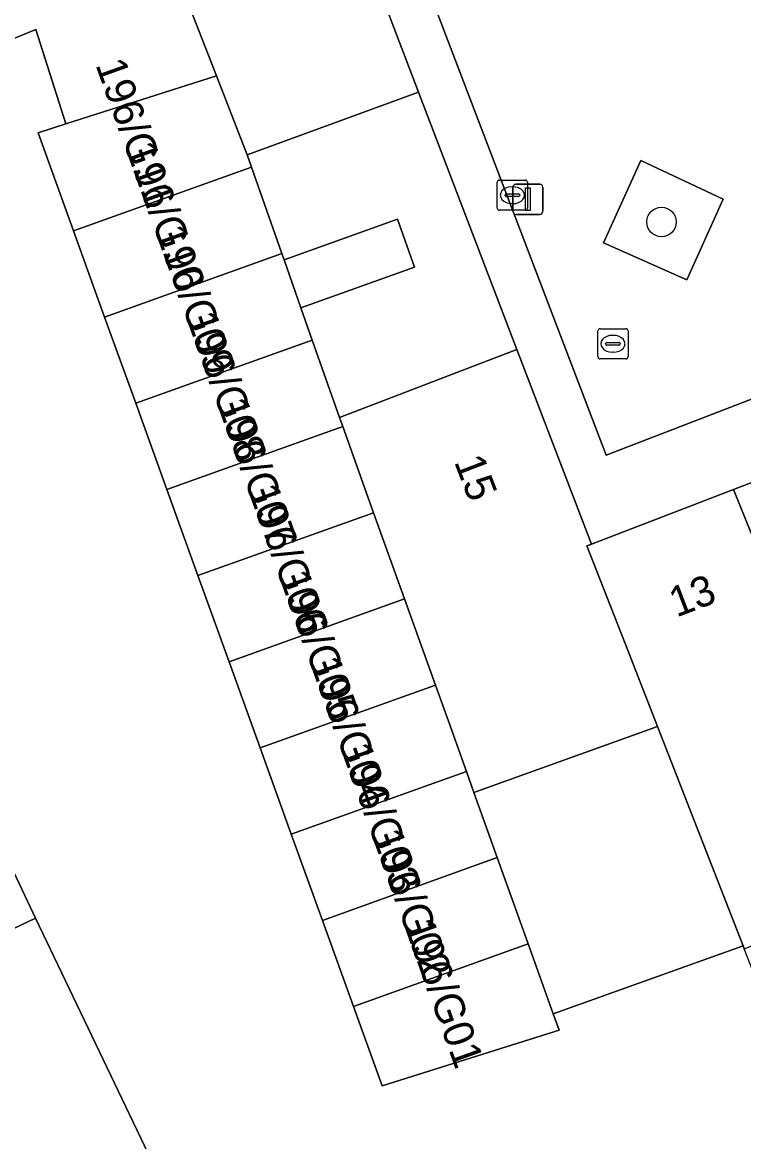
# Model space of a CAD drawing. Extents: x 159262 to 160143, y 383399 to 384319.
# Drawn here: x 159589.68 to 159613.57, y 383605.01 to 383642.07 of the extents above; entities that cross this region are included whole.
import ezdxf

# ---------------------------------------------------------------- set-up
doc = ezdxf.new("R2010")
doc.units = 0
for name, color, linetype in [('IMGEO_Boom', 7, 'Continuous'), ('IMGEO_Erf', 7, 'Continuous'), ('IMGEO_Groenvoorziening', 7, 'Continuous'), ('IMGEO_Kolk', 7, 'Continuous'), ('IMGEO_Lichtmast', 7, 'Continuous'), ('IMGEO_Muur', 7, 'Continuous'), ('IMGEO_Pand', 7, 'Continuous'), ('IMGEO_Pand_nummerreeks', 7, 'Continuous'), ('IMGEO_Rijbaan_lokaal_open', 7, 'Continuous'), ('IMGEO_Rioolput', 7, 'Continuous'), ('IMGEO_Voetpad_open', 7, 'Continuous')]:
    doc.layers.add(name, color=color, linetype=linetype)

msp = doc.modelspace()

# ---------------------------------------------------------------- linework, layer by layer
at = {"layer": 'IMGEO_Boom'}
msp.add_circle((159610.847, 383635.461), 0.489, dxfattribs=at)
at = {"layer": 'IMGEO_Erf'}
msp.add_lwpolyline([(159588.581, 383641.206), (159590.125, 383641.835), (159591.119, 383638.714), (159596.105, 383640.302), (159593.386, 383647.285), (159589.424, 383645.776)], dxfattribs=at)
for points in [[(159602.802, 383639.758), (159597.123, 383637.687), (159597.268, 383637.276), (159598.274, 383634.414), (159598.348, 383634.205), (159602.099, 383635.55), (159602.666, 383633.968), (159598.905, 383632.62), (159599.281, 383631.552), (159600.184, 383628.984), (159606.055, 383631.241)], [(159612.677, 383613.722), (159610.713, 383618.753), (159604.633, 383616.574), (159605.408, 383614.412), (159606.431, 383611.557), (159607.262, 383609.239), (159613.547, 383611.493)]]:
    msp.add_lwpolyline(points, close=True, dxfattribs=at)
at = {"layer": 'IMGEO_Groenvoorziening'}
msp.add_lwpolyline([(159611.686, 383633.54), (159612.89, 383636.214), (159610.165, 383637.494), (159608.931, 383634.775)], close=True, dxfattribs=at)
at = {"layer": 'IMGEO_Kolk'}
for p, q in [((159605.483, 383636.848), (159606.335, 383636.848)), ((159605.408, 383635.922), (159605.408, 383636.774)), ((159605.896, 383636.628), (159605.921, 383636.628)), ((159606.409, 383636.774), (159606.409, 383635.922)), ((159605.667, 383636.342), (159605.667, 383636.354)), ((159606.105, 383636.305), (159605.707, 383636.305)), ((159605.71, 383636.391), (159606.108, 383636.391)), ((159606.151, 383636.354), (159606.151, 383636.342)), ((159606.335, 383635.848), (159605.483, 383635.848)), ((159605.919, 383636.068), (159605.894, 383636.068))]:
    msp.add_line(p, q, dxfattribs=at)
for points in [[(159605.483, 383636.848), (159606.335, 383636.848)], [(159605.408, 383635.922), (159605.408, 383636.774)], [(159606.409, 383636.774), (159606.409, 383635.922)], [(159606.335, 383635.848), (159605.483, 383635.848)]]:
    msp.add_lwpolyline(points, dxfattribs=at)
for centre, radius, start, end in [((159605.485, 383636.772), 0.0765, 91.552, 178.448), ((159605.485, 383636.772), 0.0765, 91.552, 178.448), ((159606.333, 383636.772), 0.0765, 1.552, 88.448), ((159606.333, 383636.772), 0.0765, 1.552, 88.448), ((159605.707, 383636.351), 0.0403, 85.8775, 175.7526), ((159605.704, 383636.341), 0.0366, 178.938, 274.7102), ((159606.108, 383636.348), 0.043, 264.8664, 352.4533), ((159606.112, 383636.353), 0.0386, 1.7309, 96.639), ((159605.485, 383635.924), 0.0765, 181.552, 268.448), ((159605.485, 383635.924), 0.0765, 181.552, 268.448), ((159606.333, 383635.924), 0.0765, 271.552, 358.448), ((159606.333, 383635.924), 0.0765, 271.552, 358.448)]:
    msp.add_arc(centre, radius, start, end, dxfattribs=at)
for centre, major_axis, ratio, start_param, end_param in [((159605.895, 383636.348), (-0.387, 0.002), 0.722429, 4.712389, 7.853982), ((159605.92, 383636.348), (-0.39, 0.002), 0.717154, 1.570796, 4.712389)]:
    msp.add_ellipse(centre, major_axis=major_axis, ratio=ratio, start_param=start_param, end_param=end_param, dxfattribs=at)
at = {"layer": 'IMGEO_Lichtmast'}
for p, q in [((159605.922, 383635.813), (159605.922, 383636.613)), ((159605.922, 383636.613), (159605.922, 383635.813)), ((159606.022, 383636.713), (159606.812, 383636.713)), ((159606.812, 383636.713), (159606.022, 383636.713)), ((159606.912, 383636.613), (159606.912, 383635.813)), ((159606.912, 383635.813), (159606.912, 383636.613)), ((159606.812, 383635.713), (159606.022, 383635.713)), ((159606.022, 383635.713), (159606.812, 383635.713))]:
    msp.add_line(p, q, dxfattribs=at)
msp.add_lwpolyline([(159606.342, 383636.588), (159606.492, 383636.588), (159606.492, 383635.838), (159606.342, 383635.838), (159606.342, 383636.588)], dxfattribs=at)
for centre, start, end in [((159606.022, 383636.613), 90, 180), ((159606.022, 383636.613), 90, 180), ((159606.812, 383636.613), 0, 90), ((159606.812, 383636.613), 360, 90), ((159606.022, 383635.813), 180, 270), ((159606.022, 383635.813), 180, 270), ((159606.812, 383635.813), 270, 0), ((159606.812, 383635.813), 270, 0)]:
    msp.add_arc(centre, 0.1, start, end, dxfattribs=at)
at = {"layer": 'IMGEO_Muur'}
msp.add_lwpolyline([(159602.802, 383639.758), (159606.055, 383631.241)], dxfattribs=at)
at = {"layer": 'IMGEO_Pand'}
for points in [[(159599.106, 383649.464), (159596.696, 383648.546), (159593.386, 383647.285), (159596.105, 383640.302), (159597.123, 383637.687), (159602.802, 383639.758)], [(159596.105, 383640.302), (159591.119, 383638.714), (159590.201, 383638.415), (159591.375, 383635.164), (159597.268, 383637.276), (159597.123, 383637.687)], [(159598.274, 383634.414), (159597.268, 383637.276), (159591.375, 383635.164), (159592.405, 383632.31)], [(159602.099, 383635.55), (159598.348, 383634.205), (159598.905, 383632.62), (159602.666, 383633.968)], [(159598.905, 383632.62), (159598.348, 383634.205), (159598.274, 383634.414), (159592.405, 383632.31), (159593.435, 383629.457), (159599.281, 383631.552)], [(159599.281, 383631.552), (159593.435, 383629.457), (159594.465, 383626.603), (159600.289, 383628.691), (159600.184, 383628.984)], [(159608.533, 383624.793), (159606.055, 383631.241), (159600.184, 383628.984), (159600.289, 383628.691), (159601.313, 383625.835), (159602.336, 383622.98), (159603.36, 383620.124), (159603.789, 383618.926), (159604.384, 383617.268), (159604.633, 383616.574), (159610.713, 383618.753), (159609.738, 383621.249), (159608.376, 383624.733)], [(159600.289, 383628.691), (159594.465, 383626.603), (159595.495, 383623.75), (159601.313, 383625.835)], [(159618.101, 383628.463), (159613.236, 383626.597), (159617.654, 383615.665), (159622.507, 383617.561)], [(159613.236, 383626.597), (159608.533, 383624.793), (159608.376, 383624.733), (159609.738, 383621.249), (159610.713, 383618.753), (159612.677, 383613.722), (159613.547, 383611.493), (159613.585, 383611.396), (159618.589, 383613.35), (159617.654, 383615.665)], [(159602.336, 383622.98), (159601.313, 383625.835), (159595.495, 383623.75), (159596.525, 383620.896)], [(159602.336, 383622.98), (159596.525, 383620.896), (159597.555, 383618.043), (159603.36, 383620.124)], [(159598.585, 383615.19), (159604.384, 383617.268), (159603.789, 383618.926), (159603.36, 383620.124), (159597.555, 383618.043)], [(159604.633, 383616.574), (159604.384, 383617.268), (159598.585, 383615.19), (159599.615, 383612.336), (159605.408, 383614.412)], [(159583.235, 383612.589), (159584.598, 383609.776), (159590.113, 383612.405), (159588.754, 383615.263)], [(159606.431, 383611.557), (159605.408, 383614.412), (159599.615, 383612.336), (159600.646, 383609.483)], [(159598.584, 383594.73), (159590.113, 383612.405), (159584.598, 383609.776), (159581.132, 383608.123), (159582.785, 383604.655), (159579.159, 383602.927), (159585.94, 383588.702), (159593.336, 383592.228), (159596.38, 383593.679)], [(159607.262, 383609.239), (159606.431, 383611.557), (159600.646, 383609.483), (159601.595, 383606.854), (159607.455, 383608.701)]]:
    msp.add_lwpolyline(points, close=True, dxfattribs=at)
at = {"layer": 'IMGEO_Rijbaan_lokaal_open'}
for points in [[(159616.406, 383604.171), (159613.585, 383611.396), (159613.547, 383611.493), (159607.262, 383609.239), (159607.455, 383608.701), (159601.595, 383606.854), (159600.646, 383609.483), (159599.615, 383612.336), (159598.585, 383615.19), (159597.555, 383618.043), (159596.525, 383620.896), (159595.495, 383623.75), (159594.465, 383626.603), (159593.435, 383629.457), (159592.405, 383632.31), (159591.375, 383635.164), (159590.201, 383638.415), (159591.119, 383638.714), (159590.125, 383641.835), (159588.581, 383641.206)], [(159588.754, 383615.263), (159590.113, 383612.405), (159598.584, 383594.73)]]:
    msp.add_lwpolyline(points, dxfattribs=at)
at = {"layer": 'IMGEO_Rioolput'}
for p, q in [((159608.737, 383631.001), (159608.737, 383631.853)), ((159608.812, 383631.927), (159609.664, 383631.927)), ((159609.225, 383631.707), (159609.25, 383631.707)), ((159609.738, 383631.853), (159609.738, 383631.001)), ((159608.996, 383631.421), (159608.996, 383631.433)), ((159609.434, 383631.384), (159609.036, 383631.384)), ((159609.039, 383631.47), (159609.437, 383631.47)), ((159609.48, 383631.433), (159609.48, 383631.421)), ((159609.664, 383630.927), (159608.812, 383630.927)), ((159609.248, 383631.147), (159609.223, 383631.147))]:
    msp.add_line(p, q, dxfattribs=at)
for points in [[(159608.737, 383631.001), (159608.737, 383631.853)], [(159608.812, 383631.927), (159609.664, 383631.927)], [(159609.738, 383631.853), (159609.738, 383631.001)], [(159609.664, 383630.927), (159608.812, 383630.927)]]:
    msp.add_lwpolyline(points, dxfattribs=at)
for centre, radius, start, end in [((159608.814, 383631.851), 0.0765, 91.552, 178.448), ((159608.814, 383631.851), 0.0765, 91.552, 178.448), ((159609.662, 383631.851), 0.0765, 1.552, 88.448), ((159609.662, 383631.851), 0.0765, 1.552, 88.448), ((159609.036, 383631.43), 0.0403, 85.8775, 175.7526), ((159609.033, 383631.42), 0.0366, 178.938, 274.7102), ((159609.437, 383631.427), 0.043, 264.8664, 352.4533), ((159609.441, 383631.432), 0.0386, 1.7309, 96.639), ((159608.814, 383631.003), 0.0765, 181.552, 268.448), ((159608.814, 383631.003), 0.0765, 181.552, 268.448), ((159609.662, 383631.003), 0.0765, 271.552, 358.448), ((159609.662, 383631.003), 0.0765, 271.552, 358.448)]:
    msp.add_arc(centre, radius, start, end, dxfattribs=at)
for centre, major_axis, ratio, start_param, end_param in [((159609.224, 383631.427), (-0.387, 0.002), 0.722429, 4.712389, 7.853982), ((159609.249, 383631.427), (-0.39, 0.002), 0.717154, 1.570796, 4.712389)]:
    msp.add_ellipse(centre, major_axis=major_axis, ratio=ratio, start_param=start_param, end_param=end_param, dxfattribs=at)
at = {"layer": 'IMGEO_Voetpad_open'}
for points in [[(159619.379, 383631.734), (159597.575, 383688.534), (159587.311, 383684.551), (159609.011, 383627.739)], [(159609.011, 383627.739), (159587.311, 383684.551), (159597.575, 383688.534), (159619.379, 383631.734)], [(159611.686, 383633.54), (159608.931, 383634.775), (159610.165, 383637.494), (159612.89, 383636.214)]]:
    msp.add_lwpolyline(points, close=True, dxfattribs=at)
msp.add_lwpolyline([(159599.106, 383649.464), (159602.802, 383639.758), (159606.055, 383631.241), (159608.533, 383624.793), (159613.236, 383626.597), (159618.101, 383628.463), (159622.442, 383630.128), (159622.108, 383631.03), (159621.563, 383632.459), (159620.533, 383637.313), (159620.021, 383639.316), (159619.646, 383640.782), (159616.332, 383639.888), (159614.756, 383645.792)], dxfattribs=at)

# ---------------------------------------------------------------- texts
at = {"layer": 'IMGEO_Pand_nummerreeks'}
for s, rotation, p in [('196/G11', 289.7316, (159592.095, 383640.67)), ('196/G10', 289.7316, (159593.084, 383637.914)), ('196/G09', 289.7325, (159594.075, 383635.149)), ('196/G08', 289.7316, (159595.102, 383632.287)), ('196/G07', 289.7316, (159596.126, 383629.433)), ('15', 291.0273, (159603.97, 383627.523)), ('196/G06', 289.7316, (159597.15, 383626.576)), ('196/G05', 289.7316, (159598.175, 383623.72)), ('13', 20.9817, (159611.342, 383622.358)), ('196/G04', 289.7316, (159599.199, 383620.863)), ('196/G03', 289.7325, (159600.224, 383618.007)), ('196/G02', 289.7316, (159601.247, 383615.156)), ('196/G01', 289.7325, (159602.31, 383612.19))]:
    msp.add_text(s, height=1, rotation=rotation, dxfattribs=at).set_placement(p)

doc.saveas('drawing.dxf')
